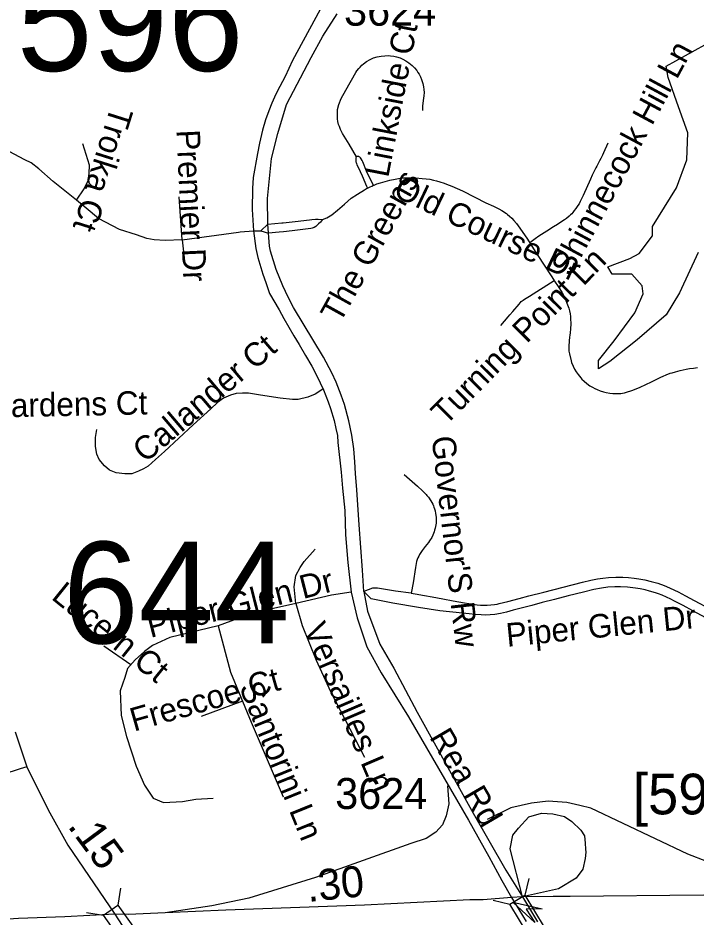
# Model space of a CAD drawing. Extents: x 1383679 to 1536984, y 460658 to 651027.
# Drawn here: x 1454668 to 1457404, y 483158 to 486789 of the extents above; entities that cross this region are included whole.
import ezdxf

# ---------------------------------------------------------------- set-up
doc = ezdxf.new("R2010")
doc.units = 0
for name, color, linetype in [('Exist Hydrographic Misc Water Feature', 7, 'Continuous'), ('Exist Road Non-System Type 51', 7, 'Continuous'), ('Exist Road Non-System Type 51 Label', 7, 'Continuous'), ('Exist Road Primary Interstate Divided Center Attributed', 7, 'Continuous'), ('Exist Road Primary Interstate Ramp 1 Lane Attributed', 7, 'Continuous'), ('Exist Road Primary Interstate Shield CELL', 7, 'Continuous'), ('Exist Road Secondary Mileage Hundredths English Label', 7, 'Continuous'), ('Exist Road Secondary Structure Standard Bridge Attributed CELL', 7, 'Continuous'), ('Exist Road Secondary Structure Standard Bridge CELL', 7, 'Continuous'), ('Exist Road Secondary Structure Standard Bridge Number Label', 7, 'Continuous'), ('Exist Road Secondary Type 51 Attributed', 7, 'Continuous'), ('Exist Road Secondary Type 51 Divided Attributed', 7, 'Continuous'), ('Exist Road Secondary Type 51 Label', 7, 'Continuous'), ('Exist Road Secondary Type 51 Number Label', 7, 'Continuous')]:
    doc.layers.add(name, color=color, linetype=linetype)

msp = doc.modelspace()

# ---------------------------------------------------------------- linework, layer by layer
at = {"layer": 'Exist Hydrographic Misc Water Feature'}
msp.add_lwpolyline([(1457413.8, 485843.2), (1457338.3, 485679.6), (1457283.8, 485591.4), (1457166.4, 485490.7), (1457057.3, 485402.6), (1457011.2, 485373.2), (1457011.2, 485406.8), (1457074.1, 485486.5), (1457158, 485599.8), (1457191.5, 485675.4), (1457187.3, 485708.9), (1457145.4, 485755.1), (1457107.6, 485755.1), (1457065.7, 485755.1), (1457048.9, 485784.5), (1457137, 485818), (1457174.7, 485839), (1457229.3, 485910.4), (1457229.3, 485948.1), (1457325.7, 486103.4), (1457367.6, 486216.7), (1457371.8, 486325.9), (1457334.1, 486430.8), (1457292.2, 486548.3), (1457283.8, 486594.4), (1457791.2, 486875.6)], dxfattribs=at)
at = {"layer": 'Exist Road Non-System Type 51'}
for p, q in [((1455330.5, 485894.2), (1455317.7, 486067.6)), ((1455648.4, 485930.6), (1455676.6, 485956.6)), ((1455330.5, 485894.2), (1455558.3, 485925.3)), ((1455618.4, 485930.5), (1455648.4, 485930.6)), ((1455648.4, 485930.6), (1455679.2, 485920.8)), ((1455330.5, 485894.2), (1455341.1, 485795.6))]:
    msp.add_line(p, q, dxfattribs=at)
for points in [[(1456033.7, 486228.6), (1456004.3, 486279.5), (1455978.1, 486322.3), (1455969.8, 486338.6), (1455965, 486350.9), (1455961.9, 486359.3), (1455959.1, 486371.1), (1455957.5, 486381.9), (1455956.8, 486395.1), (1455957.1, 486409.3), (1455958, 486419.9), (1455962.8, 486440.5), (1455972.2, 486464.1), (1455990.7, 486498.3), (1456031, 486568.5), (1456036, 486575.5), (1456043.5, 486584.8), (1456048.4, 486591.1), (1456055.1, 486597.9), (1456062.1, 486604), (1456074.6, 486613.2), (1456075, 486613.4), (1456089.7, 486621.5), (1456103, 486627.6), (1456117.1, 486632.2), (1456133.1, 486635.5), (1456149.1, 486636.8), (1456163.7, 486636.9), (1456170.7, 486636.6), (1456184.3, 486635.1), (1456195.9, 486632.6), (1456209.9, 486628.2), (1456220.9, 486623.2), (1456232.6, 486616.7), (1456245.2, 486608.6), (1456259.1, 486597.2), (1456267.9, 486588.2), (1456277.4, 486576.4), (1456282.1, 486569.4), (1456286.6, 486562.3), (1456292, 486551.9), (1456296.9, 486540.7), (1456302, 486524.2), (1456304.5, 486511.4), (1456306, 486500.6), (1456306.8, 486488.2), (1456305.7, 486474.7), (1456303.3, 486456.1), (1456301.8, 486444.1), (1456301.1, 486434.7), (1456300.7, 486422.3), (1456300.9, 486416.2)], [(1454904.3, 486054), (1454809.7, 486128.8), (1454751.3, 486180.9), (1454720.9, 486204.7), (1454695.8, 486217.1), (1454632.7, 486250), (1454546.3, 486293.1)], [(1454904.3, 486054), (1454934.6, 486099.3), (1454951, 486133.3), (1454954.5, 486161.6), (1454956.8, 486195.6), (1454928.8, 486281.7)], [(1457049.2, 486284.3), (1457031.2, 486244.6), (1457026.6, 486234.9), (1457020, 486221.9), (1457015.4, 486213.1), (1457008, 486199.4), (1457003.6, 486190.9), (1457000, 486183.8), (1456996.3, 486176.5), (1456985.9, 486155.2), (1456978.5, 486139.1), (1456948.6, 486073.1), (1456945.7, 486066.9), (1456937, 486048.4), (1456932.2, 486039.3), (1456928.1, 486032.3), (1456925.3, 486027.9), (1456922.6, 486024.2), (1456920, 486020.5), (1456913, 486011.6), (1456907.1, 486004.7), (1456902.6, 485999.4), (1456897.3, 485994.1), (1456892.3, 485989.3), (1456881.6, 485980.2), (1456873.1, 485974), (1456863.2, 485967.5), (1456845.6, 485956.2), (1456829.5, 485945.7), (1456802.6, 485928.5), (1456769.9, 485908.4), (1456755.4, 485898.6), (1456744.7, 485890.4), (1456733.5, 485881.6)], [(1456033.7, 486228.6), (1456033.4, 486228.3), (1456032.5, 486227.1), (1456031.6, 486224.7), (1456031.4, 486222.8), (1456030.9, 486219.2), (1456030.9, 486215), (1456031.1, 486212.1), (1456031.8, 486208.8), (1456032.6, 486205.6), (1456033.8, 486201.5), (1456035.4, 486197), (1456040.4, 486186.9), (1456056.8, 486151.8), (1456075, 486110.6), (1456079, 486102.5)], [(1456103.3, 486114.2), (1456080.3, 486159.1), (1456075, 486171.3), (1456059.4, 486208.6), (1456056.7, 486214.4), (1456053.5, 486220.3), (1456050.5, 486224.6), (1456048.5, 486226.7), (1456046.9, 486227.8), (1456044.8, 486229), (1456042.9, 486229.7), (1456040.9, 486230.2), (1456039.5, 486230.3), (1456037.9, 486230.3), (1456035.8, 486229.8), (1456034.4, 486229.1), (1456033.7, 486228.6)], [(1456103.3, 486114.2), (1456105.4, 486115.1), (1456116.4, 486119.2), (1456131, 486123.8), (1456149.3, 486129.7), (1456168.8, 486134.5), (1456190, 486139.2), (1456209.9, 486142.4), (1456221.1, 486143.5), (1456235, 486144.4), (1456251.5, 486144.6), (1456273.2, 486144), (1456299.3, 486142), (1456314.7, 486140.3), (1456330.1, 486138.1), (1456344.3, 486135.2), (1456356.8, 486132), (1456370, 486128.3), (1456388.3, 486122.6), (1456398, 486119.1), (1456418.9, 486110.5), (1456461.3, 486091), (1456511.9, 486065.8), (1456556.2, 486043.8), (1456586.7, 486029.7), (1456608.9, 486018.7), (1456620.6, 486011.9), (1456627.7, 486007.7), (1456633.3, 486004.1), (1456639, 486000.2), (1456643.6, 485996.6), (1456651.6, 485989.9), (1456660.7, 485981.3), (1456668.9, 485972.2), (1456679.8, 485960.4), (1456687.2, 485950), (1456721.9, 485900.3), (1456757.6, 485842.8), (1456800.1, 485779), (1456832.1, 485730.1)], [(1455896.7, 485976.5), (1455914.5, 485982.5), (1455934.7, 485994.7), (1455958, 486013.2), (1455985.2, 486038.1), (1456012.7, 486061.8), (1456037.5, 486078), (1456066.2, 486095.6), (1456075, 486100.4), (1456079, 486102.5)], [(1456079, 486102.5), (1456089.2, 486107.8), (1456095.8, 486111), (1456103.3, 486114.2)], [(1455330.5, 485894.2), (1455261.6, 485890.8), (1455217.8, 485894.2), (1455187.5, 485898.7), (1455146.6, 485914.6), (1455077.7, 485936.1), (1454992.4, 485980.3), (1454943.4, 486022.2), (1454904.3, 486054)], [(1455676.6, 485956.6), (1455732.7, 485962.1), (1455737.6, 485962.7)], [(1455737.6, 485962.7), (1455786.5, 485967.9), (1455844.7, 485974.6), (1455854.1, 485975.4), (1455869, 485976.7), (1455879.1, 485977.3), (1455896.7, 485976.5)], [(1455896.7, 485976.5), (1455888.4, 485964.7), (1455881.1, 485958.1), (1455869.7, 485947.9), (1455863.4, 485944.2), (1455855.8, 485941.2), (1455849.1, 485939.3), (1455774.5, 485930.3), (1455739.1, 485926.7)], [(1455558.3, 485925.3), (1455564.1, 485926.1), (1455618.4, 485930.5)], [(1455739.1, 485926.7), (1455721.4, 485924.9), (1455679.2, 485920.8)], [(1456616.8, 485548.4), (1456645.6, 485583.3), (1456652.4, 485591.3), (1456664.6, 485605.2), (1456690.1, 485635), (1456699.1, 485644.5), (1456706.3, 485650.7), (1456712.1, 485654.9), (1456731.9, 485667.2), (1456832.1, 485730.1)], [(1456832.1, 485730.1), (1456833.6, 485727.8), (1456848.4, 485705.9), (1456862.6, 485682.4), (1456867.9, 485673.2), (1456874, 485661.5), (1456879.3, 485649.6), (1456883.6, 485639), (1456890.8, 485618.1), (1456893.5, 485607.8), (1456896.1, 485595.4), (1456897.3, 485584.5), (1456897.9, 485576.7), (1456898.6, 485555.1), (1456898, 485534.9), (1456896.6, 485519.2), (1456895.4, 485509.6), (1456894, 485501.9), (1456892.1, 485486.4), (1456891, 485463.1), (1456890.9, 485457.4), (1456891.7, 485445.4), (1456893.7, 485434.3), (1456900.3, 485405.8), (1456902.4, 485399.2), (1456908.6, 485384.4), (1456914.4, 485372.5), (1456921.4, 485360.8), (1456928.2, 485350.9), (1456939, 485337.3), (1456943.4, 485332.4), (1456953, 485323.8), (1456964.2, 485314.1), (1456976.2, 485305.4), (1456986.9, 485299), (1456996, 485293.8), (1457005.3, 485289.5), (1457018.2, 485284.4), (1457030.9, 485280.3), (1457041.3, 485277.8), (1457056.5, 485275.6), (1457068.6, 485274.3), (1457080, 485273.7), (1457089.8, 485273.8), (1457100.7, 485274.6), (1457107.5, 485275.3), (1457116.4, 485277.2), (1457128.1, 485280.3), (1457141, 485284.1), (1457150.1, 485287.6), (1457179.1, 485299.9), (1457224.7, 485321.1), (1457262.3, 485339.4), (1457272.1, 485344), (1457283.9, 485348.9), (1457300.8, 485355.4), (1457308.9, 485358), (1457321.1, 485361.5), (1457340.4, 485366.6), (1457364.3, 485371.6), (1457378.4, 485374.2), (1457394.1, 485376.6), (1457410.3, 485378.5)], [(1455897.6, 485291), (1455867.6, 485271.7), (1455837.7, 485258.9), (1455799.1, 485250.3), (1455775.5, 485250.3), (1455726.3, 485254.6), (1455647, 485267.5), (1455597.8, 485276), (1455574.2, 485276), (1455548.5, 485273.9), (1455525, 485267.5), (1455497.1, 485254.6), (1455473.6, 485237.5), (1455445.7, 485211.7), (1455375, 485147.4), (1455259.4, 485040.3), (1455223, 485008.1), (1455193, 484980.3), (1455173.7, 484969.5), (1455154.4, 484961), (1455126.6, 484950.3), (1455098.8, 484950.3), (1455064.5, 484954.5), (1455036.7, 484965.3), (1455017.4, 484982.4), (1454996, 485008.1), (1454985.3, 485029.6), (1454981, 485059.6), (1454981, 485096), (1454985.3, 485128.1)], [(1456226.6, 484947.6), (1456280.7, 484899.7), (1456300.7, 484880.8), (1456307.6, 484874.4), (1456314.7, 484866.8), (1456318.5, 484862.1), (1456324.1, 484855.2), (1456334.3, 484841), (1456338.5, 484834.1), (1456342.1, 484827.3), (1456345.1, 484820.3), (1456346.9, 484815.3), (1456349, 484808.5), (1456351.1, 484800.2), (1456353.5, 484789.7), (1456355.7, 484775.3), (1456356.1, 484767.8), (1456356.1, 484761), (1456355.2, 484751.4), (1456354.1, 484744.5), (1456351.3, 484730.3), (1456349.5, 484722.5), (1456347.3, 484715.8), (1456342, 484701.9), (1456337.7, 484693.1), (1456329.3, 484679.9), (1456324.4, 484673), (1456311.8, 484657.1), (1456299.7, 484641), (1456294, 484633), (1456288.8, 484624.7), (1456285.1, 484618.1), (1456282, 484611.1), (1456279.1, 484603.7), (1456276.9, 484595.8), (1456272.2, 484572.6), (1456262.9, 484509.8), (1456255.3, 484468.1)], [(1455788.9, 484426.8), (1455783.1, 484493.7), (1455788.9, 484540.1), (1455806.5, 484571.8), (1455822.8, 484596.8), (1455867.2, 484646.6)], [(1456255.3, 484468.1), (1456270.8, 484466.1), (1456308.7, 484459.3), (1456340, 484453.8), (1456382.3, 484445.4), (1456424.3, 484437.6), (1456469.7, 484429.5), (1456505.6, 484423.8), (1456521.7, 484421.8), (1456534.9, 484420.4), (1456549.7, 484419.6), (1456562.1, 484419.8), (1456576, 484420.9), (1456590.5, 484422.4), (1456601.4, 484424.3), (1456609.8, 484426.4), (1456644.4, 484435.4), (1456691.3, 484447.4), (1456730, 484457.5), (1456789.9, 484472.3), (1456867.8, 484492.6), (1456946.1, 484512.7), (1456980, 484521.2), (1457006.5, 484526.5), (1457028.3, 484529.4), (1457051.5, 484531.8), (1457080.6, 484533.2), (1457108.9, 484532.9), (1457132.2, 484531.4), (1457155, 484529.6), (1457173.5, 484526.8), (1457198, 484521.9), (1457224, 484515.9), (1457249.8, 484508.4), (1457276, 484499.2), (1457297.5, 484490.3), (1457317.8, 484481.1), (1457332, 484474), (1457362.3, 484457.1), (1457396.9, 484438.3), (1457462.4, 484403.7)], [(1456012.4, 484472.2), (1455932.6, 484460.8), (1455788.9, 484426.8)], [(1457444.1, 484368.4), (1457392.1, 484396.8), (1457352.6, 484418.2), (1457317.7, 484436.8), (1457302.5, 484444.9), (1457285.2, 484453), (1457268, 484460.2), (1457253.3, 484466.1), (1457241, 484470.1), (1457217.4, 484476.8), (1457198.8, 484481.8), (1457179.6, 484485.6), (1457160, 484489), (1457128.1, 484492.3), (1457099.2, 484493.5), (1457076.4, 484493.7), (1457048.9, 484492.1), (1457023.3, 484489.1), (1456992.4, 484483.3), (1456949.8, 484472.5), (1456889, 484457.9), (1456832.9, 484442.9), (1456783.5, 484430.2), (1456741.8, 484419.3), (1456703.7, 484409.6), (1456666.4, 484399.9), (1456640.2, 484392.5), (1456615.7, 484387.1), (1456592.5, 484382.7), (1456573.3, 484380.8), (1456555, 484380.1), (1456537.4, 484380.5), (1456514.9, 484382.7), (1456370.6, 484397.3), (1456284.1, 484410.9), (1456181.4, 484427.9), (1456093.1, 484445.6), (1456063.2, 484475.6)], [(1456255.3, 484468.1), (1456191.6, 484476.5), (1456118.6, 484488.4), (1456098.9, 484488.9), (1456063.2, 484475.6)], [(1455788.9, 484426.8), (1455614.9, 484388.3), (1455475.9, 484336.2)], [(1455788.9, 484426.8), (1455814.6, 484338.4), (1455870.7, 484197.9), (1455929.1, 484072.1), (1456066.9, 483807)], [(1455475.9, 484336.2), (1455280.9, 484289.7), (1455210.8, 484258), (1455178.1, 484233), (1455140.8, 484199.1), (1455110.4, 484165.1), (1455098.7, 484128.8), (1455080, 484074.4), (1455084.7, 483974.7), (1455105.7, 483890.8), (1455145.4, 483770.7), (1455178.1, 483693.7), (1455213.2, 483641.6), (1455255.2, 483623.4), (1455332.3, 483628), (1455386, 483637), (1455456.1, 483641.6)], [(1455475.9, 484336.2), (1455525, 484150.3), (1455609.1, 483948.6), (1455737.6, 483647.2)], [(1455123, 484179.2), (1455013.7, 484254.4)], [(1455574.2, 484032.2), (1455407.2, 483970.8)], [(1454703.8, 483767.6), (1454675.9, 483760.4), (1454644.3, 483749.6), (1454614.6, 483740.5), (1454540.2, 483746), (1454401.4, 483773), (1454326.2, 483793.2), (1454124.6, 483840.8), (1454010.2, 483871.6), (1453991.6, 483876.5)]]:
    msp.add_lwpolyline(points, dxfattribs=at)
at = {"layer": 'Exist Road Primary Interstate Divided Center Attributed'}
for points in [[(1455058.1, 483174.1), (1454856.2, 483163), (1454669.9, 483156.3), (1454250.6, 483127.5), (1453955.4, 483118.4), (1453391.7, 483122.5), (1452990.4, 483167.3), (1452697.6, 483220.6), (1452247.2, 483318.2), (1451136.4, 483601.3), (1450902.3, 483655.9), (1450490.8, 483714.5), (1450011.1, 483764.3), (1449962, 483766.7), (1449456.7, 483790), (1449281.9, 483785.1)], [(1456659.3, 483240.4), (1456544.7, 483231), (1456491.4, 483231), (1456066.8, 483209.7), (1455506.2, 483189.6), (1455262.2, 483178.5)], [(1456703.7, 483242.9), (1456659.3, 483240.4)], [(1458156.8, 483240.7), (1458060.3, 483241.4), (1457433.5, 483249.6), (1456896.7, 483245.2), (1456827.9, 483245.2), (1456703.7, 483242.9)], [(1455262.2, 483178.5), (1455113.6, 483171.9), (1455058.1, 483174.1)]]:
    msp.add_lwpolyline(points, dxfattribs=at)
at = {"layer": 'Exist Road Primary Interstate Ramp 1 Lane Attributed'}
for points in [[(1456401, 483690.7), (1456404.6, 483655.2), (1456406.4, 483618.9), (1456396.6, 483570), (1456380.6, 483533.7), (1456354.9, 483504.4), (1456315.9, 483478.6), (1456253, 483458.2), (1455868, 483321.6), (1455599.4, 483238.5), (1455450.8, 483207.4), (1455262.2, 483178.5)], [(1458156.8, 483240.7), (1457808.5, 483280.7), (1457602.1, 483327.3), (1457371.4, 483416.1), (1456980.1, 483600.9), (1456935.6, 483612), (1456883.1, 483624.6), (1456808.1, 483629.8), (1456740.1, 483621.5), (1456657.2, 483603), (1456561.8, 483555.3)], [(1456688.6, 483520), (1456729.9, 483565.5), (1456780.9, 483580.7), (1456826.1, 483578.8), (1456873.2, 483567.4), (1456903.3, 483547.1), (1456940.2, 483512.1), (1456954, 483489.3), (1456956.6, 483460.5), (1456958.5, 483435.7)], [(1456703.7, 483242.9), (1456653.7, 483437.6), (1456665.2, 483492.1), (1456688.6, 483520)], [(1456958.5, 483435.7), (1456959.5, 483423.3), (1456956.6, 483398.3), (1456947.4, 483355.3), (1456921.1, 483318.4), (1456850.1, 483276.2), (1456703.7, 483242.9)]]:
    msp.add_lwpolyline(points, dxfattribs=at)
at = {"layer": 'Exist Road Secondary Structure Standard Bridge Attributed CELL'}
msp.add_lwpolyline([(1456754.5, 483139.7), (1456664.9, 483222.4), (1456783.9, 483195.6), (1456718.9, 483194.1)], close=True, dxfattribs=at)
at = {"layer": 'Exist Road Secondary Structure Standard Bridge CELL'}
for p, q in [((1456730.1, 483317), (1456713.6, 483250)), ((1455081.6, 483278.1), (1455070.3, 483210)), ((1456586.2, 483229.9), (1456653.2, 483213.5)), ((1454944.8, 483180.4), (1455012.8, 483169))]:
    msp.add_line(p, q, dxfattribs=at)
for points in [[(1456713.6, 483250), (1456791.8, 483120.7), (1456731.4, 483084.2), (1456653.2, 483213.5)], [(1455070.3, 483210), (1455158.1, 483087.1), (1455100.6, 483046), (1455012.8, 483169)]]:
    msp.add_lwpolyline(points, close=True, dxfattribs=at)
at = {"layer": 'Exist Road Secondary Type 51 Attributed'}
for points in [[(1454656.7, 483909.2), (1454703.8, 483767.6), (1454788.9, 483594.5), (1454868.4, 483451.8), (1455058.1, 483174.1)], [(1455058.1, 483174.1), (1455088.1, 483127.5), (1455135.8, 483072)]]:
    msp.add_lwpolyline(points, dxfattribs=at)
at = {"layer": 'Exist Road Secondary Type 51 Divided Attributed'}
for points in [[(1455887.6, 486823.4), (1455775.5, 486617.1), (1455745.9, 486552.4), (1455725.3, 486513), (1455708.8, 486481), (1455691.9, 486445), (1455679.8, 486414), (1455666.9, 486377.5), (1455654.7, 486336.6), (1455642.9, 486284.1), (1455634.8, 486242.4), (1455616.7, 486145.7), (1455614.3, 486100.4), (1455612.6, 486016.6), (1455618.4, 485930.5), (1455627.8, 485859.1), (1455635.9, 485822.8), (1455655.8, 485756), (1455667.5, 485722), (1455682.7, 485677.8), (1455722.2, 485611.2), (1455740.5, 485575.9), (1455781.7, 485506.1), (1455802.4, 485471.9), (1455827.7, 485427.5), (1455854, 485384.4), (1455871.8, 485350.4), (1455887.7, 485316.5), (1455900.6, 485288.2), (1455919.9, 485240), (1455929.5, 485212.8), (1455943.3, 485164.7), (1455951.1, 485132.7), (1455957, 485104.1), (1455958.9, 485076.1), (1455972.6, 484956.4), (1455977.6, 484892), (1455986.5, 484802), (1455989.8, 484703.3), (1455998.6, 484592.2), (1456012.4, 484472.2)], [(1456063.2, 484475.6), (1456057.9, 484561.6), (1456044.5, 484743.6), (1456035.6, 484884.7), (1456030.4, 484951.8), (1456027.3, 484998.2), (1456023.3, 485050.7), (1456015.6, 485106.5), (1456003.3, 485164), (1455985.3, 485230), (1455972.3, 485267), (1455951.4, 485319.3), (1455934, 485357.4), (1455901.5, 485420.7), (1455780.2, 485621.3), (1455758.2, 485662.4), (1455736.9, 485707.8), (1455710.1, 485773.7), (1455686.8, 485848), (1455682.9, 485867.8), (1455676.6, 485956.6), (1455674.5, 486060.8), (1455690.8, 486221.7), (1455716.5, 486322.5), (1455751.7, 486439.7), (1455850.7, 486629.9), (1455897.8, 486715.2), (1455956, 486805.7)], [(1456012.4, 484472.2), (1456036.6, 484369.1), (1456075.9, 484252.4), (1456134.2, 484147.7), (1456244.4, 483969.2), (1456486.7, 483552.3)], [(1456063.2, 484475.6), (1456079, 484395.7), (1456128.8, 484263.4), (1456184.9, 484165.4), (1456279.6, 483988), (1456504.5, 483580.4)], [(1456504.5, 483580.4), (1456637, 483351), (1456703.7, 483242.9)], [(1456486.7, 483552.3), (1456567.6, 483405.7), (1456620.2, 483308.9), (1456659.3, 483240.4)], [(1456659.3, 483240.4), (1456719.2, 483144)], [(1456703.7, 483242.9), (1456765.3, 483142.1)]]:
    msp.add_lwpolyline(points, dxfattribs=at)

# ---------------------------------------------------------------- texts
at = {"layer": 'Exist Road Non-System Type 51 Label'}
for s, rotation, p in [('Linkside Ct', 79.082, (1456162.1, 486142.2)), ('Shinnecock Hill Ln', 61.7293, (1456898.8, 485741.7)), ('Troika Ct', 252.5327, (1455042.9, 486437.7)), ('Premier Dr', 272.6907, (1455306.9, 486336.6)), ('The Greens', 61.0005, (1455967.1, 485553.8)), ('Old Course Dr', 334.514, (1456177.4, 486072.1)), ('Turning Point Ln', 45.3692, (1456393.9, 485141.6)), ('Callander Ct', 40.3415, (1455181.4, 484991.1)), ('Kensington Gardens Ct', 1.1705, (1453870.2, 485162.7)), ("Governor'S Rw", 276.5582, (1456337, 485097.9)), ('Piper Glen Dr', 14.3111, (1455202.2, 484287.5)), ('Lucern Ct', 321.2049, (1454798.2, 484447.4)), ('Piper Glen Dr', 5.6944, (1456642.4, 484251.8)), ('Versailles Ln', 293.1986, (1455818.1, 484325.2)), ('Frescoe Ct', 15.8582, (1455135.7, 483909.5)), ('Santorini Ln', 292.0625, (1455559.3, 484090.1))]:
    msp.add_text(s, height=95, rotation=rotation, dxfattribs=at).set_placement(p)
at = {"layer": 'Exist Road Primary Interstate Shield CELL'}
msp.add_text('[59]', height=164.04, dxfattribs=at).set_placement((1457149.8, 483576.1))
at = {"layer": 'Exist Road Secondary Mileage Hundredths English Label'}
for s, rotation, p in [('.15', 306.5249, (1454865.1, 483528.5)), ('.30', 6.0324, (1455838.8, 483222.4))]:
    msp.add_text(s, height=125, rotation=rotation, dxfattribs=at).set_placement(p)
at = {"layer": 'Exist Road Secondary Structure Standard Bridge Number Label'}
for s, p in [('596', (1454663, 486575.4)), ('644', (1454849.5, 484265.8))]:
    msp.add_text(s, height=410.1, dxfattribs=at).set_placement(p)
at = {"layer": 'Exist Road Secondary Type 51 Label'}
msp.add_text('Rea Rd', height=95, rotation=300.3434, dxfattribs=at).set_placement((1456326.5, 483887.9))
at = {"layer": 'Exist Road Secondary Type 51 Number Label'}
for p in [(1455983.8, 486757.8), (1455948, 483597.8)]:
    msp.add_text('3624', height=125, dxfattribs=at).set_placement(p)

doc.saveas('drawing.dxf')
